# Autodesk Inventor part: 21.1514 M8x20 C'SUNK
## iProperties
Created: 2006-12
Part Number: 21.1514 M8x20 C'SUNK
Material: Steel, Mild
Description: Hexagon socket countersunk head cap screws
Document SubType Name: Modeling
Standard: DIN 7991
Designer: Andy Moles
Standards Organization: DIN
Language: en-US
Size Designation: M8x20
Categories: <MemberInstance Version="R10.0.0"><Categories><Category DisplayName="Fasteners" InternalName="e4da775c-781d-43d5-af7c-5136215cf5a6" Mnemonic="FSTN"><Category Di
Density: 7.86 g/cm^3
Mass: 9.85186 g
Surface Area: 9.27162 cm^2
Volume: 1.25342 cm^3
Author: Andy Moles
Revision Number: 1
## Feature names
1. Revolution1
2. Extrusion1
3. Fillet1
4. Chamfer1
